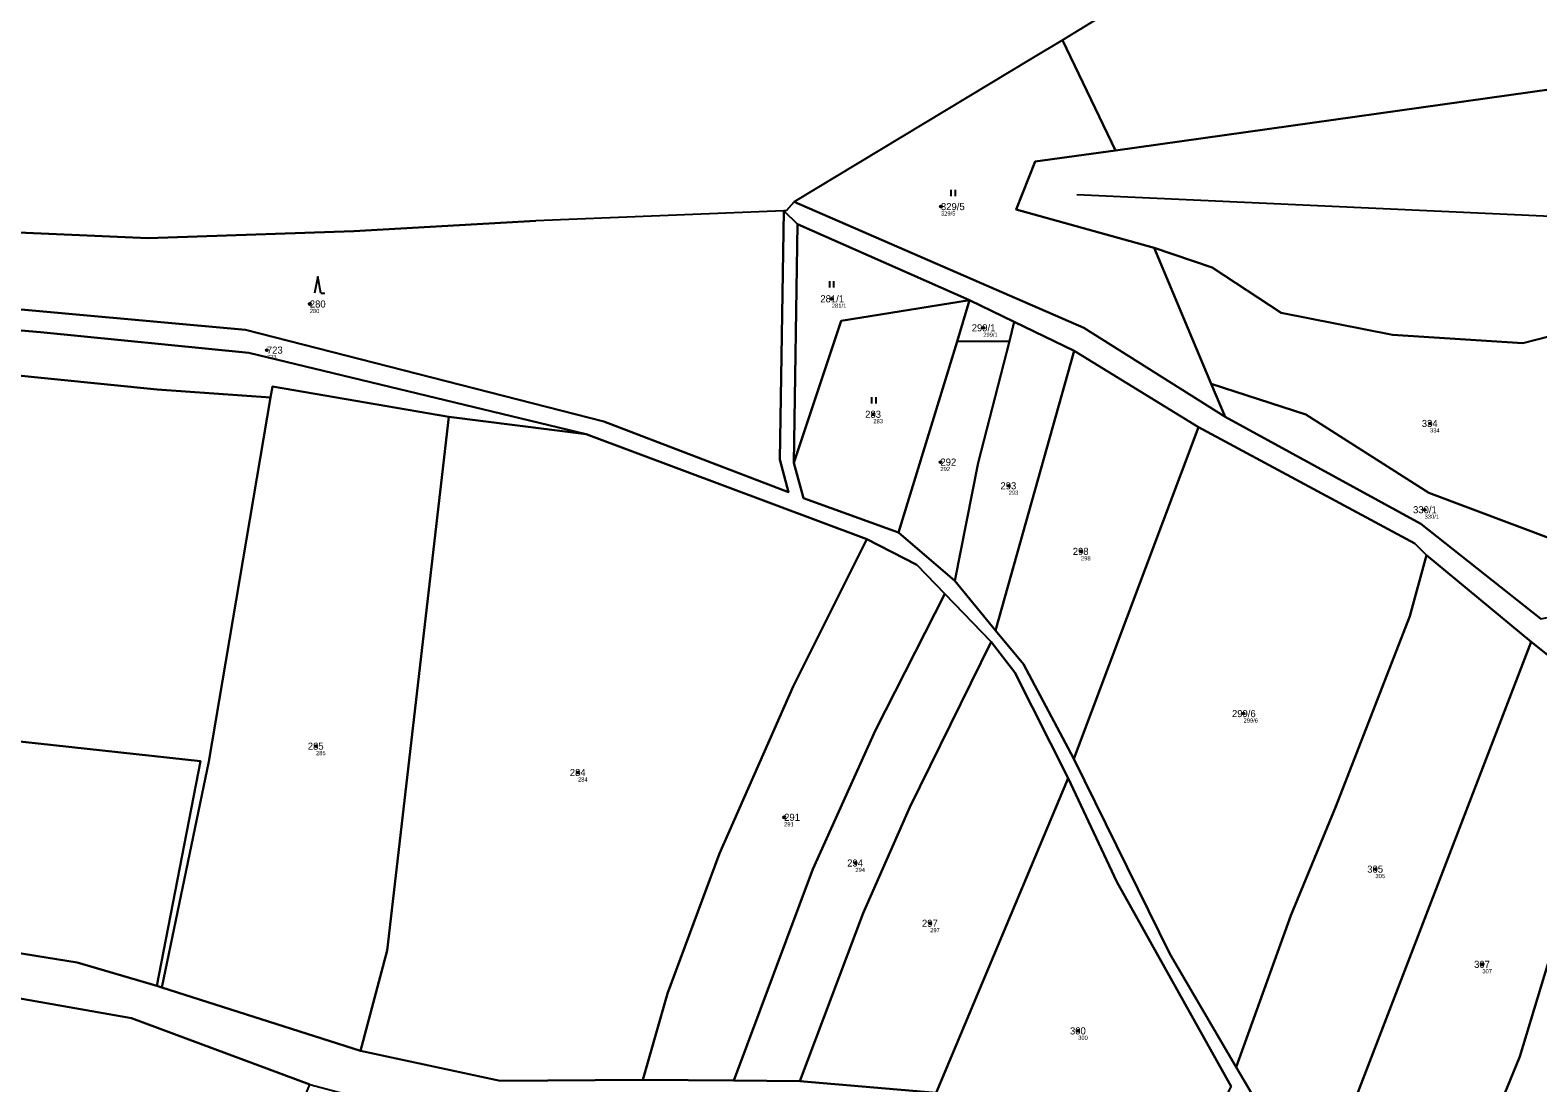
# Model space of a CAD drawing. Extents: x -767985 to -763816, y -1059600 to -1057360.
# Drawn here: x -766543.5 to -766182.2, y -1058107.9 to -1057855.6 of the extents above; entities that cross this region are included whole.
import ezdxf

# ---------------------------------------------------------------- set-up
doc = ezdxf.new("R2010")
doc.units = 0
for name, color, linetype in [('Definiční body', 7, 'Continuous'), ('Hranice parcel', 7, 'Continuous'), ('Parcelní čísla', 7, 'Continuous'), ('Polygon ku', 7, 'Continuous'), ('Polygon parcely', 7, 'Continuous'), ('Vnitřní kresba', 7, 'Continuous'), ('Značky kultur', 7, 'Continuous')]:
    doc.layers.add(name, color=color, linetype=linetype)

msp = doc.modelspace()

# ---------------------------------------------------------------- linework, layer by layer
at = {"layer": 'Definiční body'}
for centre in [(-766325.24, -1057897.86994), (-766351.37, -1057919.95994), (-766476.51, -1057921.21994), (-766315.09, -1057926.91994), (-766486.8, -1057932.26994), (-766341.43, -1057947.63994), (-766208.01, -1057949.83994), (-766325.36, -1057959.09994), (-766309, -1057964.77994), (-766209.31, -1057970.51994), (-766291.67, -1057980.49994), (-766252.71, -1058019.36994), (-766475.02, -1058027.17994), (-766412.22, -1058033.48994), (-766362.82, -1058044.22994), (-766345.74, -1058055.17994), (-766221.09, -1058056.64994), (-766327.82, -1058069.61994), (-766195.48, -1058079.45994), (-766292.34, -1058095.40994)]:
    msp.add_circle(centre, 0.25, dxfattribs=at)
at = {"layer": 'Hranice parcel'}
for p, q in [((-766288.25, -1057853.23), (-766296.07, -1057857.95)), ((-766296.07, -1057857.95), (-766303.42, -1057862.38)), ((-766296.07, -1057857.95), (-766283.39, -1057884.39)), ((-766303.42, -1057862.38), (-766360.41, -1057896.76)), ((-766362.22, -1057898.84), (-766360.41, -1057896.76)), ((-766362.9, -1057898.87), (-766422.32, -1057901.25)), ((-766362.22, -1057898.84), (-766362.9, -1057898.87)), ((-766359.63, -1057902.1), (-766362.9, -1057898.87)), ((-766359.63, -1057902.1), (-766360.46, -1057959.26)), ((-766318.43, -1057920.31), (-766359.63, -1057902.1)), ((-766260.5, -1057940.33), (-766274.1, -1057907.73)), ((-766318.43, -1057920.31), (-766321.36, -1057930.23)), ((-766307.72, -1057925.48), (-766318.43, -1057920.31)), ((-766308.81, -1057930.15), (-766307.72, -1057925.48)), ((-766307.72, -1057925.48), (-766293.28, -1057932.44)), ((-766321.36, -1057930.23), (-766335.44, -1057976)), ((-766321.36, -1057930.23), (-766308.81, -1057930.15)), ((-766312.18, -1057999.43), (-766293.28, -1057932.44)), ((-766293.28, -1057932.44), (-766263.53, -1057950.77)), ((-766257.09, -1057948.29), (-766260.5, -1057940.33)), ((-766410.25, -1057952.37), (-766443.15, -1057948.23)), ((-766342.97, -1057977.58), (-766410.25, -1057952.37)), ((-766293.36, -1058030.24), (-766263.53, -1057950.77)), ((-766321.92, -1057987.58), (-766335.44, -1057976)), ((-766183.79, -1058002.15), (-766208.88, -1057981.37)), ((-766312.18, -1057999.43), (-766321.92, -1057987.58)), ((-766324.32, -1057990.68), (-766313.23, -1058002.19)), ((-766326.41, -1058110.25), (-766294.77, -1058034.83)), ((-766511.94, -1058085.05), (-766513.2, -1058084.65)), ((-766511.94, -1058085.05), (-766464.33, -1058100.19)), ((-766254.48, -1058104.1), (-766237.19, -1058133.37)), ((-766396.68, -1058107.11), (-766374.9, -1058107.31)), ((-766359.08, -1058107.45), (-766374.9, -1058107.31)), ((-766359.08, -1058107.45), (-766326.41, -1058110.25))]:
    msp.add_line(p, q, dxfattribs=at)
for points in [[(-766283.39, -1057884.39), (-766163.03, -1057867.49), (-766163.37, -1057821.27), (-766143.81, -1057780.24), (-766067.8, -1057790.53), (-765987.71, -1057789.24), (-765958.7, -1057796.52)], [(-766274.1, -1057907.73), (-766307.22, -1057898.6), (-766302.67, -1057887.1), (-766283.39, -1057884.39)], [(-766690.81, -1057898.52), (-766577.57, -1057919.64), (-766491.94, -1057927.39), (-766406.06, -1057949.34), (-766361.79, -1057966.34), (-766363.82, -1057958.47), (-766362.9, -1057898.87)], [(-766360.41, -1057896.76), (-766291, -1057926.89), (-766257.09, -1057948.29)], [(-766700.85, -1057899.26), (-766642.29, -1057912.13), (-766571.66, -1057925.32), (-766541.02, -1057928), (-766491.13, -1057932.92), (-766410.25, -1057952.37)], [(-766583.09, -1057902.51), (-766515.27, -1057905.45), (-766465.97, -1057903.73), (-766422.32, -1057901.25)], [(-766274.1, -1057907.73), (-766260.24, -1057912.44), (-766243.67, -1057923.34), (-766216.98, -1057928.64), (-766185.76, -1057930.57), (-766159.27, -1057923.82)], [(-766485.9, -1057943.62), (-766513.07, -1057941.74), (-766574.26, -1057935.56), (-766621.45, -1057928.98), (-766696.65, -1057912.81)], [(-766360.46, -1057959.26), (-766349.14, -1057925.26), (-766318.43, -1057920.31)], [(-766321.92, -1057987.58), (-766316.34, -1057959.28), (-766308.81, -1057930.15)], [(-766443.15, -1057948.23), (-766485.44, -1057940.96), (-766485.9, -1057943.62)], [(-766177.71, -1057977.96), (-766208.34, -1057966.44), (-766237.75, -1057947.66), (-766260.5, -1057940.33)], [(-766485.9, -1057943.62), (-766500.72, -1058030.88), (-766511.94, -1058085.05)], [(-766443.15, -1057948.23), (-766457.98, -1058076.12), (-766464.33, -1058100.19)], [(-766181.44, -1057996.63), (-766210.21, -1057973.93), (-766257.09, -1057948.29)], [(-766263.53, -1057950.77), (-766211.68, -1057978.59), (-766208.88, -1057981.37)], [(-766335.44, -1057976), (-766358.22, -1057967.72), (-766360.46, -1057959.26)], [(-766396.68, -1058107.11), (-766390.75, -1058086.46), (-766378.33, -1058052.91), (-766360.64, -1058012.85), (-766342.97, -1057977.58)], [(-766324.32, -1057990.68), (-766330.99, -1057983.75), (-766342.97, -1057977.58)], [(-766208.88, -1057981.37), (-766212.85, -1057996.05), (-766230.56, -1058041.64), (-766241.37, -1058067.72), (-766254.48, -1058104.1)], [(-766374.9, -1058107.31), (-766355.94, -1058056.68), (-766340.92, -1058023.35), (-766324.32, -1057990.68)], [(-766293.36, -1058030.24), (-766305.49, -1058007.56), (-766312.18, -1057999.43)], [(-766313.23, -1058002.19), (-766332.72, -1058041.81), (-766343.9, -1058067.16), (-766359.08, -1058107.45)], [(-766294.77, -1058034.83), (-766307.56, -1058009.54), (-766313.23, -1058002.19)], [(-766237.19, -1058133.37), (-766226.1, -1058112.24), (-766183.79, -1058002.15)], [(-766183.79, -1058002.15), (-766167.63, -1058015.06), (-766159.54, -1058029.12)], [(-766513.2, -1058084.65), (-766502.69, -1058030.74), (-766565.21, -1058024.02), (-766698.79, -1058013.2)], [(-766254.48, -1058104.1), (-766270.41, -1058076.92), (-766293.36, -1058030.24)], [(-766211.74, -1058159.91), (-766197.74, -1058129.1), (-766186.48, -1058101.56), (-766171.41, -1058051.74), (-766159.54, -1058029.12)], [(-766255.67, -1058108.72), (-766283.05, -1058059.71), (-766294.77, -1058034.83)], [(-766697.67, -1058052.38), (-766532.25, -1058079.05), (-766513.2, -1058084.65)], [(-766650.5, -1058070.18), (-766591.82, -1058079.56), (-766519.26, -1058092.35), (-766476.48, -1058108.27)], [(-766464.33, -1058100.19), (-766430.89, -1058107.39), (-766396.68, -1058107.11)]]:
    msp.add_lwpolyline(points, dxfattribs=at)
at = {"layer": 'Polygon ku'}
msp.add_lwpolyline([(-766288.25, -1057853.23), (-766296.07, -1057857.95), (-766303.42, -1057862.38), (-766360.41, -1057896.76), (-766362.22, -1057898.84), (-766362.9, -1057898.87), (-766422.32, -1057901.25), (-766465.97, -1057903.73), (-766515.27, -1057905.45), (-766583.09, -1057902.51)], dxfattribs=at)
at = {"layer": 'Polygon parcely'}
for points in [[(-765958.7, -1057796.52), (-765949.04, -1057674.96), (-765935.63, -1057628.93), (-765978.04, -1057682.92), (-765994.07, -1057702.71), (-766011.37, -1057724.06), (-766053.4, -1057768.29), (-766167.45, -1057777.61), (-766182.03, -1057786.39), (-766194.48, -1057793.89), (-766241.5, -1057825.03), (-766245.83, -1057827.64), (-766288.25, -1057853.23), (-766296.07, -1057857.95), (-766283.39, -1057884.39), (-766163.03, -1057867.49), (-766163.37, -1057821.27), (-766143.81, -1057780.24), (-766067.8, -1057790.53), (-765987.71, -1057789.24)], [(-765764.71, -1057828.11), (-765785.43, -1057807.92), (-765889.74, -1057801.06), (-765958.7, -1057796.52), (-765987.71, -1057789.24), (-766067.8, -1057790.53), (-766143.81, -1057780.24), (-766163.37, -1057821.27), (-766163.03, -1057867.49), (-766283.39, -1057884.39), (-766302.67, -1057887.1), (-766307.22, -1057898.6), (-766274.1, -1057907.73), (-766260.24, -1057912.44), (-766243.67, -1057923.34), (-766216.98, -1057928.64), (-766185.76, -1057930.57), (-766159.27, -1057923.82), (-766133.45, -1057919.58), (-766086.05, -1057916.3), (-766035.43, -1057948.89), (-765897.96, -1057981.9), (-765887.36, -1057969.44)], [(-766257.09, -1057948.29), (-766260.5, -1057940.33), (-766274.1, -1057907.73), (-766307.22, -1057898.6), (-766302.67, -1057887.1), (-766283.39, -1057884.39), (-766296.07, -1057857.95), (-766303.42, -1057862.38), (-766360.41, -1057896.76), (-766291, -1057926.89)], [(-766577.57, -1057919.64), (-766491.94, -1057927.39), (-766406.06, -1057949.34), (-766361.79, -1057966.34), (-766363.82, -1057958.47), (-766362.9, -1057898.87), (-766422.32, -1057901.25), (-766465.97, -1057903.73), (-766515.27, -1057905.45), (-766583.09, -1057902.51), (-766607.66, -1057901.45), (-766684.18, -1057898.76), (-766690.81, -1057898.52)], [(-766700.85, -1057899.26), (-766701.3, -1057911.68), (-766696.65, -1057912.81), (-766621.45, -1057928.98), (-766574.26, -1057935.56), (-766513.07, -1057941.74), (-766485.9, -1057943.62), (-766485.44, -1057940.96), (-766443.15, -1057948.23), (-766410.25, -1057952.37), (-766491.13, -1057932.92), (-766541.02, -1057928), (-766571.66, -1057925.32), (-766642.29, -1057912.13)], [(-766349.14, -1057925.26), (-766318.43, -1057920.31), (-766359.63, -1057902.1), (-766360.46, -1057959.26)], [(-766274.1, -1057907.73), (-766260.5, -1057940.33), (-766237.75, -1057947.66), (-766208.34, -1057966.44), (-766177.71, -1057977.96), (-766165.68, -1057940.49), (-766159.27, -1057923.82), (-766185.76, -1057930.57), (-766216.98, -1057928.64), (-766243.67, -1057923.34), (-766260.24, -1057912.44)], [(-766485.9, -1057943.62), (-766513.07, -1057941.74), (-766574.26, -1057935.56), (-766621.45, -1057928.98), (-766696.65, -1057912.81), (-766698.79, -1058013.2), (-766565.21, -1058024.02), (-766502.69, -1058030.74), (-766513.2, -1058084.65), (-766511.94, -1058085.05), (-766500.72, -1058030.88)], [(-766318.43, -1057920.31), (-766349.14, -1057925.26), (-766360.46, -1057959.26), (-766358.22, -1057967.72), (-766335.44, -1057976), (-766321.36, -1057930.23)], [(-766321.36, -1057930.23), (-766308.81, -1057930.15), (-766307.72, -1057925.48), (-766318.43, -1057920.31)], [(-766312.18, -1057999.43), (-766293.28, -1057932.44), (-766307.72, -1057925.48), (-766308.81, -1057930.15), (-766316.34, -1057959.28), (-766321.92, -1057987.58)], [(-766316.34, -1057959.28), (-766308.81, -1057930.15), (-766321.36, -1057930.23), (-766335.44, -1057976), (-766321.92, -1057987.58)], [(-766293.36, -1058030.24), (-766263.53, -1057950.77), (-766293.28, -1057932.44), (-766312.18, -1057999.43), (-766305.49, -1058007.56)], [(-766485.9, -1057943.62), (-766500.72, -1058030.88), (-766511.94, -1058085.05), (-766464.33, -1058100.19), (-766457.98, -1058076.12), (-766443.15, -1057948.23), (-766485.44, -1057940.96)], [(-766260.5, -1057940.33), (-766257.09, -1057948.29), (-766210.21, -1057973.93), (-766181.44, -1057996.63), (-766146.46, -1057989.81), (-766151.39, -1057989.18), (-766167.12, -1057982.55), (-766177.71, -1057977.96), (-766208.34, -1057966.44), (-766237.75, -1057947.66)], [(-766378.33, -1058052.91), (-766360.64, -1058012.85), (-766342.97, -1057977.58), (-766410.25, -1057952.37), (-766443.15, -1057948.23), (-766457.98, -1058076.12), (-766464.33, -1058100.19), (-766430.89, -1058107.39), (-766396.68, -1058107.11), (-766390.75, -1058086.46)], [(-766254.48, -1058104.1), (-766241.37, -1058067.72), (-766230.56, -1058041.64), (-766212.85, -1057996.05), (-766208.88, -1057981.37), (-766211.68, -1057978.59), (-766263.53, -1057950.77), (-766293.36, -1058030.24), (-766270.41, -1058076.92)], [(-766355.94, -1058056.68), (-766340.92, -1058023.35), (-766324.32, -1057990.68), (-766330.99, -1057983.75), (-766342.97, -1057977.58), (-766360.64, -1058012.85), (-766378.33, -1058052.91), (-766390.75, -1058086.46), (-766396.68, -1058107.11), (-766374.9, -1058107.31)], [(-766237.19, -1058133.37), (-766226.1, -1058112.24), (-766183.79, -1058002.15), (-766208.88, -1057981.37), (-766212.85, -1057996.05), (-766230.56, -1058041.64), (-766241.37, -1058067.72), (-766254.48, -1058104.1)], [(-766324.32, -1057990.68), (-766340.92, -1058023.35), (-766355.94, -1058056.68), (-766374.9, -1058107.31), (-766359.08, -1058107.45), (-766343.9, -1058067.16), (-766332.72, -1058041.81), (-766313.23, -1058002.19)], [(-766343.9, -1058067.16), (-766359.08, -1058107.45), (-766326.41, -1058110.25), (-766294.77, -1058034.83), (-766307.56, -1058009.54), (-766313.23, -1058002.19), (-766332.72, -1058041.81)], [(-766211.74, -1058159.91), (-766197.74, -1058129.1), (-766186.48, -1058101.56), (-766171.41, -1058051.74), (-766159.54, -1058029.12), (-766167.63, -1058015.06), (-766183.79, -1058002.15), (-766226.1, -1058112.24), (-766237.19, -1058133.37), (-766227.03, -1058144.31), (-766224.05, -1058147.52)], [(-766697.67, -1058052.38), (-766532.25, -1058079.05), (-766513.2, -1058084.65), (-766502.69, -1058030.74), (-766565.21, -1058024.02), (-766698.79, -1058013.2)], [(-766190.76, -1058186.25), (-766175.72, -1058156.75), (-766155.9, -1058094.1), (-766139.56, -1058061.14), (-766159.54, -1058029.12), (-766171.41, -1058051.74), (-766186.48, -1058101.56), (-766197.74, -1058129.1), (-766211.74, -1058159.91), (-766194.86, -1058176.88)], [(-766264.36, -1058126.45), (-766255.67, -1058108.72), (-766283.05, -1058059.71), (-766294.77, -1058034.83), (-766326.41, -1058110.25), (-766292.75, -1058116.53)], [(-766615.09, -1058249.35), (-766608.27, -1058140.01), (-766546.08, -1058150.89), (-766551.64, -1058182.48), (-766558.76, -1058284.36), (-766566.83, -1058336.99), (-766540.99, -1058342.11), (-766497.44, -1058159.16), (-766476.48, -1058108.27), (-766519.26, -1058092.35), (-766591.82, -1058079.56), (-766650.5, -1058070.18), (-766657.51, -1058120.99), (-766663.5, -1058195.07), (-766666.99, -1058239.99), (-766668.24, -1058266.92), (-766671.98, -1058304.33), (-766674.15, -1058332.27), (-766666.46, -1058330.33), (-766623.36, -1058334.07)]]:
    msp.add_lwpolyline(points, close=True, dxfattribs=at)
for points in [[(-766181.44, -1057996.63), (-766210.21, -1057973.93), (-766257.09, -1057948.29), (-766291, -1057926.89), (-766360.41, -1057896.76), (-766362.22, -1057898.84), (-766362.9, -1057898.87), (-766359.63, -1057902.1), (-766318.43, -1057920.31), (-766307.72, -1057925.48), (-766293.28, -1057932.44), (-766263.53, -1057950.77), (-766211.68, -1057978.59), (-766208.88, -1057981.37), (-766183.79, -1058002.15), (-766167.63, -1058015.06)], [(-766237.19, -1058133.37), (-766254.48, -1058104.1), (-766270.41, -1058076.92), (-766293.36, -1058030.24), (-766305.49, -1058007.56), (-766312.18, -1057999.43), (-766321.92, -1057987.58), (-766335.44, -1057976), (-766358.22, -1057967.72), (-766360.46, -1057959.26), (-766359.63, -1057902.1), (-766362.9, -1057898.87), (-766363.82, -1057958.47), (-766361.79, -1057966.34), (-766406.06, -1057949.34), (-766491.94, -1057927.39), (-766577.57, -1057919.64)], [(-766571.66, -1057925.32), (-766541.02, -1057928), (-766491.13, -1057932.92), (-766410.25, -1057952.37), (-766342.97, -1057977.58), (-766330.99, -1057983.75), (-766324.32, -1057990.68), (-766313.23, -1058002.19), (-766307.56, -1058009.54), (-766294.77, -1058034.83), (-766283.05, -1058059.71), (-766255.67, -1058108.72)], [(-766179.98, -1058204.86), (-766190.76, -1058186.25), (-766194.86, -1058176.88), (-766211.74, -1058159.91), (-766224.05, -1058147.52), (-766227.03, -1058144.31), (-766238.61, -1058137.56), (-766264.36, -1058126.45), (-766292.75, -1058116.53), (-766326.41, -1058110.25), (-766359.08, -1058107.45), (-766374.9, -1058107.31), (-766396.68, -1058107.11), (-766430.89, -1058107.39), (-766464.33, -1058100.19), (-766511.94, -1058085.05), (-766513.2, -1058084.65), (-766532.25, -1058079.05), (-766697.67, -1058052.38)], [(-766591.82, -1058079.56), (-766519.26, -1058092.35), (-766476.48, -1058108.27), (-766453.88, -1058114.27), (-766427.44, -1058118.16), (-766399.42, -1058117.63), (-766380.1, -1058116.76), (-766362.46, -1058116.57), (-766330.16, -1058120.06), (-766297.4, -1058125.29), (-766264.92, -1058136.59), (-766238.31, -1058148.79), (-766224.55, -1058161.19), (-766213.18, -1058175.32), (-766194.8, -1058201.72), (-766183.4, -1058221.59), (-766169.87, -1058250.23)]]:
    msp.add_lwpolyline(points, dxfattribs=at)
at = {"layer": 'Vnitřní kresba'}
msp.add_line((-766177.33, -1057900.33), (-766292.64, -1057895.04), dxfattribs=at)
at = {"layer": 'Značky kultur'}
for p, q in [((-766322.761, -1057895.34), (-766322.761, -1057893.84)), ((-766321.76, -1057895.34), (-766321.76, -1057893.84)), ((-766474.62, -1057914.61), (-766475.37, -1057918.61)), ((-766473.87, -1057918.61), (-766474.62, -1057914.61)), ((-766351.881, -1057917.26), (-766351.881, -1057915.76)), ((-766350.88, -1057917.26), (-766350.88, -1057915.76)), ((-766473.87, -1057918.61), (-766472.874, -1057918.61)), ((-766341.791, -1057945.03), (-766341.791, -1057943.53)), ((-766340.79, -1057945.03), (-766340.79, -1057943.53))]:
    msp.add_line(p, q, dxfattribs=at)

# ---------------------------------------------------------------- texts
at = {"layer": 'Definiční body'}
for s, p in [('329/5', (-766325.24, -1057900.026)), ('280', (-766476.51, -1057923.376)), ('281/1', (-766351.37, -1057922.116)), ('299/1', (-766315.09, -1057929.076)), ('723', (-766486.8, -1057934.426)), ('283', (-766341.43, -1057949.796)), ('334', (-766208.01, -1057951.996)), ('292', (-766325.36, -1057961.256)), ('293', (-766309, -1057966.936)), ('330/1', (-766209.31, -1057972.676)), ('298', (-766291.67, -1057982.656)), ('299/6', (-766252.71, -1058021.526)), ('285', (-766475.02, -1058029.336)), ('284', (-766412.22, -1058035.646)), ('291', (-766362.82, -1058046.386)), ('294', (-766345.74, -1058057.336)), ('305', (-766221.09, -1058058.806)), ('297', (-766327.82, -1058071.776)), ('307', (-766195.48, -1058081.616)), ('300', (-766292.34, -1058097.566))]:
    msp.add_text(s, height=0.999996, dxfattribs=at).set_placement(p)
at = {"layer": 'Parcelní čísla'}
for s, p in [('329/5', (-766325.24, -1057898.72)), ('280', (-766476.51, -1057922.07)), ('281/1', (-766354.143, -1057920.81)), ('299/1', (-766317.863, -1057927.77)), ('723', (-766486.8, -1057933.12)), ('283', (-766343.404, -1057948.49)), ('334', (-766209.984, -1057950.69)), ('292', (-766325.36, -1057959.95)), ('293', (-766310.974, -1057965.63)), ('330/1', (-766212.083, -1057971.37)), ('298', (-766293.644, -1057981.35)), ('299/6', (-766255.483, -1058020.22)), ('285', (-766476.994, -1058028.03)), ('284', (-766414.194, -1058034.34)), ('291', (-766362.82, -1058045.08)), ('294', (-766347.714, -1058056.03)), ('305', (-766223.064, -1058057.5)), ('297', (-766329.794, -1058070.47)), ('307', (-766197.454, -1058080.31)), ('300', (-766294.314, -1058096.26))]:
    msp.add_text(s, height=1.699998, dxfattribs=at).set_placement(p)

doc.saveas('drawing.dxf')
